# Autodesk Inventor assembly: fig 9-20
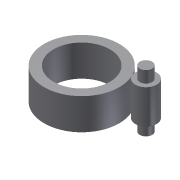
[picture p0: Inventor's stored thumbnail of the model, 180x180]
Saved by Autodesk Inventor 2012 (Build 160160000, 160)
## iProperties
Shininess: 64.0
Length Units: 11269
Angle Units: 11279
Time Units: 11290
Mass Units: 11283
Length Display Precision: 3
Angle Display Precision: 2
Created: 2002-01
Part Number: fig 9-20
Document SubType Name: Assembly
Designer: ***
Density: 0.0
Volumn: 0.0
Area: 0.0
PropertySet Name: Model Information
Control State: 0
Master: False
Checked Out: False
Author: ***
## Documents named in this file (3)
- C:\Users\CadCim\Documents\SAILESH\inventor-2011-fact-prt\c09_inv_2011-prt\c09_inv_2012_prt\fig 9-20.iam
- C:\Users\CadCim\Documents\SAILESH\inventor-2011-fact-prt\c09_inv_2011-prt\c09_inv_2012_prt\Part8.ipt
- C:\Users\CadCim\Documents\SAILESH\inventor-2011-fact-prt\c09_inv_2011-prt\Part9.ipt
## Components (2 placed, 2 different names)
1. Part8:1 — Flush:1
2. Part9:1 — Flush:1
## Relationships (1: Flush 1)
- Flush:1: Part8:1 ↔ Part9:1
